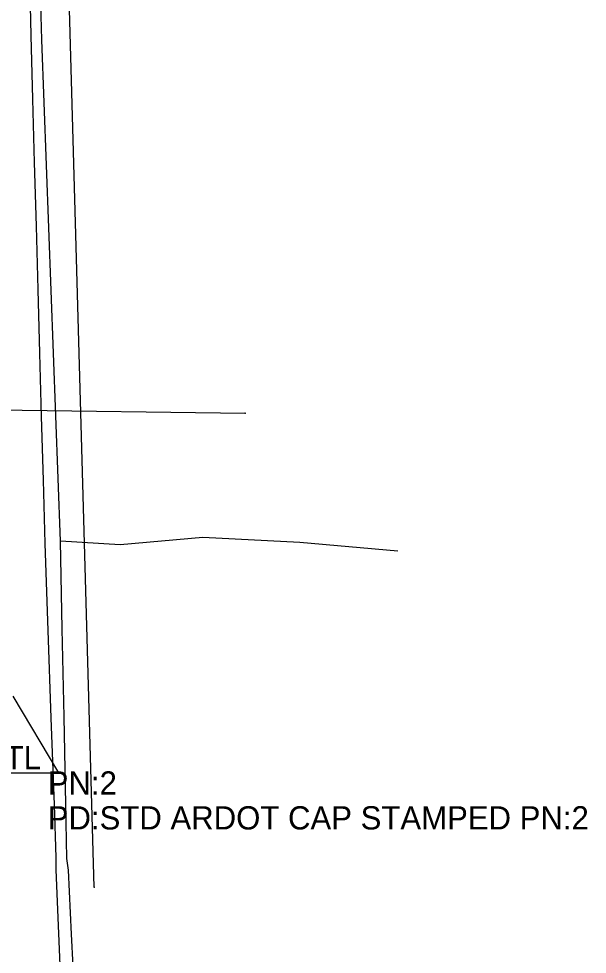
# Model space of a CAD drawing. Extents: x 1930288 to 1941089, y 588389 to 611475.
# Drawn here: x 1930923.3 to 1931045.5, y 597126 to 597327.2 of the extents above; entities that cross this region are included whole.
import ezdxf

# ---------------------------------------------------------------- set-up
doc = ezdxf.new("R2010")
doc.units = 0
for name, color, linetype in [('S_DITCHLINE', 7, 'Continuous'), ('S_PRIMARY_CTL', 7, 'Continuous'), ('S_PRIMARY_CTL_ANNOT', 7, 'Continuous'), ('S_SANITARY_SEWER', 7, 'Continuous'), ('S_UTL_PT_SYM', 7, 'Continuous'), ('S_WATER_UTILITIES', 7, 'Continuous')]:
    doc.layers.add(name, color=color, linetype=linetype)

msp = doc.modelspace()

# ---------------------------------------------------------------- linework, layer by layer
at = {"layer": 'S_DITCHLINE'}
for points in [[(1930932.51, 597116.8), (1930931.93, 597130.48), (1930931.34, 597144.16), (1930931.37, 597146.85), (1930930.97, 597158.18), (1930930.31, 597176.9), (1930929.65, 597195.63), (1930928.98, 597214.35), (1930928.61, 597228.01), (1930928.23, 597241.67), (1930927.86, 597255.33), (1930927.49, 597268.99), (1930927.11, 597282.65), (1930926.74, 597296.31), (1930926.36, 597309.96), (1930925.99, 597323.62), (1930925.67, 597336.44)], [(1930935.37, 597116.58), (1930934.68, 597130.34), (1930934, 597144.1), (1930933.68, 597146.64), (1930933.45, 597158.21), (1930933.06, 597177.11), (1930932.67, 597196), (1930932.29, 597214.9), (1930931.79, 597228.38), (1930931.29, 597241.85), (1930930.79, 597255.33), (1930930.29, 597268.81), (1930929.79, 597282.29), (1930929.29, 597295.76), (1930928.79, 597309.24), (1930928.29, 597322.72), (1930927.95, 597335.64)], [(1931004.76, 597212.75), (1930983.71, 597214.6), (1930962.87, 597215.63), (1930945.14, 597214.11), (1930932.29, 597214.9)]]:
    msp.add_lwpolyline(points, dxfattribs=at)
at = {"layer": 'S_PRIMARY_CTL'}
for p in [(1930922.05, 597181.56), (1930912.01, 597165.04)]:
    msp.add_line(p, (1930931.87, 597165.04), dxfattribs=at)
at = {"layer": 'S_SANITARY_SEWER'}
msp.add_line((1930939.56, 597140.44), (1930923.55, 597706.51), dxfattribs=at)
at = {"layer": 'S_UTL_PT_SYM'}
for points in [[(1930971.97, 597242.4), (1930971.97, 597242.45), (1930971.97, 597242.4), (1930971.92, 597242.4), (1930971.97, 597242.4), (1930971.97, 597242.35), (1930971.97, 597242.4), (1930972.02, 597242.4)], [(1930939.56, 597140.44), (1930939.56, 597140.49), (1930939.56, 597140.44), (1930939.51, 597140.44), (1930939.56, 597140.44), (1930939.56, 597140.39), (1930939.56, 597140.44), (1930939.61, 597140.44)]]:
    msp.add_lwpolyline(points, dxfattribs=at)
at = {"layer": 'S_WATER_UTILITIES'}
msp.add_line((1930857.41, 597243.98), (1930971.97, 597242.4), dxfattribs=at)

# ---------------------------------------------------------------- texts
at = {"layer": 'S_PRIMARY_CTL'}
msp.add_text('CTL', height=5, rotation=360, dxfattribs=at).set_placement((1930915.46, 597165.78))
at = {"layer": 'S_PRIMARY_CTL_ANNOT'}
for s, p in [('PN:2', (1930929.55, 597160.36)), ('PD:STD ARDOT CAP STAMPED PN:2', (1930929.55, 597152.86))]:
    msp.add_text(s, height=5, dxfattribs=at).set_placement(p)

doc.saveas('drawing.dxf')
